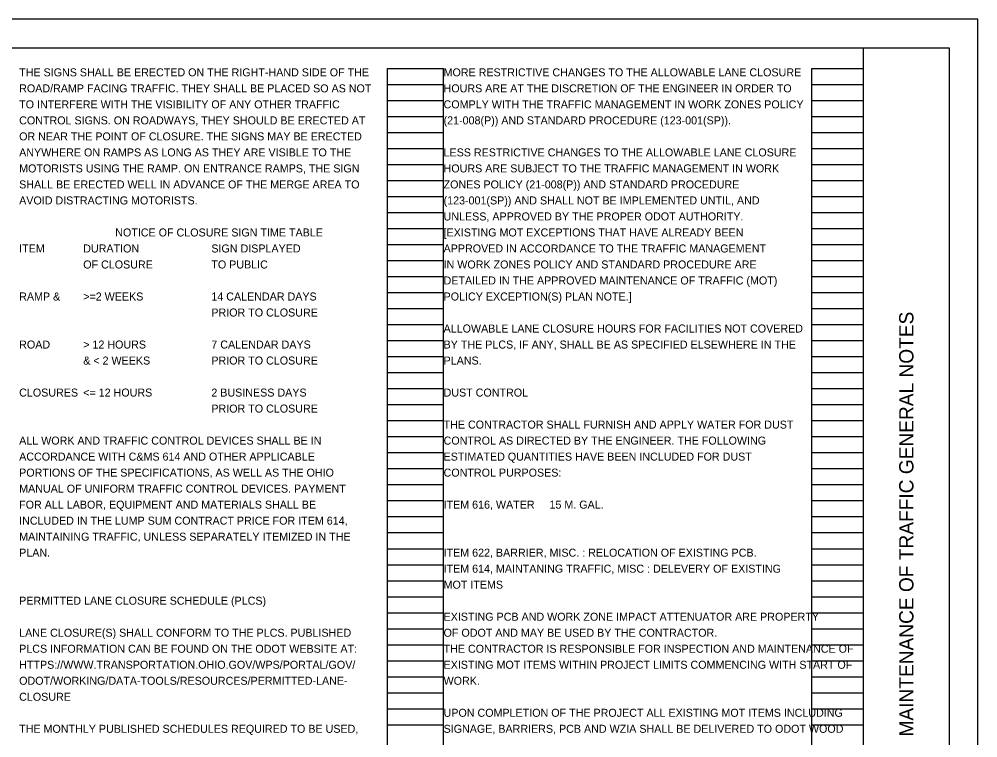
# Model space of a CAD drawing. Extents: x -53 to 237, y -2 to 24.
# Drawn here: x -36.25 to -19.49, y 11.09 to 23.66 of the extents above; entities that cross this region are included whole.
import ezdxf

# ---------------------------------------------------------------- set-up
doc = ezdxf.new("R2010")
doc.units = 0
for name, color, linetype in [('SH_Text', 7, 'Continuous'), ('SN_P_Signs', 7, 'Continuous'), ('SN_X_Text', 7, 'Continuous')]:
    doc.layers.add(name, color=color, linetype=linetype)

msp = doc.modelspace()

# ---------------------------------------------------------------- linework, layer by layer
at = {"layer": 'SH_Text'}
for p, q in [((-29.814, 2.643), (-29.814, 22.803)), ((-29.814, 22.803), (-28.834, 22.803)), ((-28.834, 2.643), (-28.834, 22.803)), ((-22.394, 2.643), (-22.394, 22.803)), ((-22.394, 22.803), (-21.494, 22.803)), ((-21.494, 2.643), (-21.494, 22.803)), ((-29.814, 22.523), (-28.834, 22.523)), ((-22.394, 22.523), (-21.494, 22.523)), ((-29.814, 22.243), (-28.834, 22.243)), ((-22.394, 22.243), (-21.494, 22.243)), ((-29.814, 21.963), (-28.834, 21.963)), ((-22.394, 21.963), (-21.494, 21.963)), ((-29.814, 21.683), (-28.834, 21.683)), ((-22.394, 21.683), (-21.494, 21.683)), ((-29.814, 21.403), (-28.834, 21.403)), ((-22.394, 21.403), (-21.494, 21.403)), ((-29.814, 21.123), (-28.834, 21.123)), ((-22.394, 21.123), (-21.494, 21.123)), ((-29.814, 20.843), (-28.834, 20.843)), ((-22.394, 20.843), (-21.494, 20.843)), ((-29.814, 20.563), (-28.834, 20.563)), ((-22.394, 20.563), (-21.494, 20.563)), ((-29.814, 20.283), (-28.834, 20.283)), ((-22.394, 20.283), (-21.494, 20.283)), ((-29.814, 20.003), (-28.834, 20.003)), ((-22.394, 20.003), (-21.494, 20.003)), ((-29.814, 19.723), (-28.834, 19.723)), ((-22.394, 19.723), (-21.494, 19.723)), ((-29.814, 19.443), (-28.834, 19.443)), ((-22.394, 19.443), (-21.494, 19.443)), ((-29.814, 19.163), (-28.834, 19.163)), ((-22.394, 19.163), (-21.494, 19.163)), ((-29.814, 18.883), (-28.834, 18.883)), ((-22.394, 18.883), (-21.494, 18.883)), ((-29.814, 18.603), (-28.834, 18.603)), ((-22.394, 18.603), (-21.494, 18.603)), ((-29.814, 18.323), (-28.834, 18.323)), ((-22.394, 18.323), (-21.494, 18.323)), ((-29.814, 18.043), (-28.834, 18.043)), ((-22.394, 18.043), (-21.494, 18.043)), ((-29.814, 17.763), (-28.834, 17.763)), ((-22.394, 17.763), (-21.494, 17.763)), ((-29.814, 17.483), (-28.834, 17.483)), ((-22.394, 17.483), (-21.494, 17.483)), ((-29.814, 17.203), (-28.834, 17.203)), ((-22.394, 17.203), (-21.494, 17.203)), ((-29.814, 16.923), (-28.834, 16.923)), ((-22.394, 16.923), (-21.494, 16.923)), ((-29.814, 16.643), (-28.834, 16.643)), ((-22.394, 16.643), (-21.494, 16.643)), ((-29.814, 16.363), (-28.834, 16.363)), ((-22.394, 16.363), (-21.494, 16.363)), ((-29.814, 16.083), (-28.834, 16.083)), ((-22.394, 16.083), (-21.494, 16.083)), ((-29.814, 15.803), (-28.834, 15.803)), ((-22.394, 15.803), (-21.494, 15.803)), ((-29.814, 15.523), (-28.834, 15.523)), ((-22.394, 15.523), (-21.494, 15.523)), ((-29.814, 15.243), (-28.834, 15.243)), ((-22.394, 15.243), (-21.494, 15.243)), ((-29.814, 14.963), (-28.834, 14.963)), ((-22.394, 14.963), (-21.494, 14.963)), ((-29.814, 14.683), (-28.834, 14.683)), ((-22.394, 14.683), (-21.494, 14.683)), ((-29.814, 14.403), (-28.834, 14.403)), ((-22.394, 14.403), (-21.494, 14.403)), ((-29.814, 14.123), (-28.834, 14.123)), ((-22.394, 14.123), (-21.494, 14.123)), ((-29.814, 13.843), (-28.834, 13.843)), ((-22.394, 13.843), (-21.494, 13.843)), ((-29.814, 13.563), (-28.834, 13.563)), ((-22.394, 13.563), (-21.494, 13.563)), ((-29.814, 13.283), (-28.834, 13.283)), ((-22.394, 13.283), (-21.494, 13.283)), ((-29.814, 13.003), (-28.834, 13.003)), ((-22.394, 13.003), (-21.494, 13.003)), ((-29.814, 12.723), (-28.834, 12.723)), ((-22.394, 12.723), (-21.494, 12.723)), ((-29.814, 12.443), (-28.834, 12.443)), ((-22.394, 12.443), (-21.494, 12.443)), ((-29.814, 12.163), (-28.834, 12.163)), ((-22.394, 12.163), (-21.494, 12.163)), ((-29.814, 11.883), (-28.834, 11.883)), ((-22.394, 11.883), (-21.494, 11.883)), ((-29.814, 11.603), (-28.834, 11.603)), ((-22.394, 11.603), (-21.494, 11.603)), ((-29.814, 11.323), (-28.834, 11.323)), ((-22.394, 11.323), (-21.494, 11.323))]:
    msp.add_line(p, q, dxfattribs=at)
at = {"layer": 'SN_X_Text'}
msp.add_line((-21.494, 2.163), (-21.494, 23.163), dxfattribs=at)
for points in [[(-53.494, 1.663), (-19.494, 1.663), (-19.494, 23.663), (-53.494, 23.663)], [(-51.994, 23.163), (-19.994, 23.163), (-19.994, 2.163), (-51.994, 2.163)]]:
    msp.add_lwpolyline(points, close=True, dxfattribs=at)

# ---------------------------------------------------------------- texts
at = {"layer": 'SN_P_Signs'}
for s, p in [('THE SIGNS SHALL BE ERECTED ON THE RIGHT-HAND SIDE OF THE', (-36.254, 22.663)), ('MORE RESTRICTIVE CHANGES TO THE ALLOWABLE LANE CLOSURE', (-28.834, 22.663)), ('ROAD/RAMP FACING TRAFFIC. THEY SHALL BE PLACED SO AS NOT', (-36.254, 22.383)), ('HOURS ARE AT THE DISCRETION OF THE ENGINEER IN ORDER TO', (-28.834, 22.383)), ('TO INTERFERE WITH THE VISIBILITY OF ANY OTHER TRAFFIC', (-36.254, 22.103)), ('COMPLY WITH THE TRAFFIC MANAGEMENT IN WORK ZONES POLICY', (-28.834, 22.103)), ('CONTROL SIGNS. ON ROADWAYS, THEY SHOULD BE ERECTED AT', (-36.254, 21.823)), ('(21-008(P)) AND STANDARD PROCEDURE (123-001(SP)).', (-28.834, 21.823)), ('OR NEAR THE POINT OF CLOSURE. THE SIGNS MAY BE ERECTED', (-36.254, 21.543)), ('ANYWHERE ON RAMPS AS LONG AS THEY ARE VISIBLE TO THE', (-36.254, 21.263)), ('LESS RESTRICTIVE CHANGES TO THE ALLOWABLE LANE CLOSURE', (-28.834, 21.263)), ('MOTORISTS USING THE RAMP. ON ENTRANCE RAMPS, THE SIGN', (-36.254, 20.983)), ('HOURS ARE SUBJECT TO THE TRAFFIC MANAGEMENT IN WORK', (-28.834, 20.983)), ('SHALL BE ERECTED WELL IN ADVANCE OF THE MERGE AREA TO', (-36.254, 20.703)), ('ZONES POLICY (21-008(P)) AND STANDARD PROCEDURE', (-28.834, 20.703)), ('AVOID DISTRACTING MOTORISTS.', (-36.254, 20.423)), ('(123-001(SP)) AND SHALL NOT BE IMPLEMENTED UNTIL, AND', (-28.834, 20.423)), ('UNLESS, APPROVED BY THE PROPER ODOT AUTHORITY.', (-28.834, 20.143)), ('NOTICE OF CLOSURE SIGN TIME TABLE', (-34.574, 19.863)), ('[EXISTING MOT EXCEPTIONS THAT HAVE ALREADY BEEN', (-28.834, 19.863)), ('ITEM       ', (-36.254, 19.583)), ('DURATION       ', (-35.134, 19.583)), ('SIGN DISPLAYED', (-32.894, 19.583)), ('APPROVED IN ACCORDANCE TO THE TRAFFIC MANAGEMENT', (-28.834, 19.583)), ('OF CLOSURE     ', (-35.134, 19.303)), ('TO PUBLIC', (-32.894, 19.303)), ('IN WORK ZONES POLICY AND STANDARD PROCEDURE ARE', (-28.834, 19.303)), ('DETAILED IN THE APPROVED MAINTENANCE OF TRAFFIC (MOT)', (-28.834, 19.023)), ('RAMP &     ', (-36.254, 18.743)), ('>=2 WEEKS      ', (-35.134, 18.743)), ('14 CALENDAR DAYS', (-32.894, 18.743)), ('POLICY EXCEPTION(S) PLAN NOTE.]', (-28.834, 18.743)), ('PRIOR TO CLOSURE', (-32.894, 18.463)), ('ALLOWABLE LANE CLOSURE HOURS FOR FACILITIES NOT COVERED', (-28.834, 18.183)), ('ROAD       ', (-36.254, 17.903)), ('> 12 HOURS     ', (-35.134, 17.903)), ('7 CALENDAR DAYS', (-32.894, 17.903)), ('BY THE PLCS, IF ANY, SHALL BE AS SPECIFIED ELSEWHERE IN THE', (-28.834, 17.903)), ('& < 2 WEEKS    ', (-35.134, 17.623)), ('PRIOR TO CLOSURE', (-32.894, 17.623)), ('PLANS.', (-28.834, 17.623)), ('CLOSURES   ', (-36.254, 17.063)), ('<= 12 HOURS    ', (-35.134, 17.063)), ('2 BUSINESS DAYS', (-32.894, 17.063)), ('DUST CONTROL', (-28.834, 17.063)), ('PRIOR TO CLOSURE', (-32.894, 16.783)), ('THE CONTRACTOR SHALL FURNISH AND APPLY WATER FOR DUST', (-28.834, 16.503)), ('ALL WORK AND TRAFFIC CONTROL DEVICES SHALL BE IN', (-36.254, 16.223)), ('CONTROL AS DIRECTED BY THE ENGINEER. THE FOLLOWING', (-28.834, 16.223)), ('ACCORDANCE WITH C&MS 614 AND OTHER APPLICABLE', (-36.254, 15.943)), ('ESTIMATED QUANTITIES HAVE BEEN INCLUDED FOR DUST', (-28.834, 15.943)), ('PORTIONS OF THE SPECIFICATIONS, AS WELL AS THE OHIO', (-36.254, 15.663)), ('CONTROL PURPOSES:', (-28.834, 15.663)), ('MANUAL OF UNIFORM TRAFFIC CONTROL DEVICES. PAYMENT', (-36.254, 15.383)), ('FOR ALL LABOR, EQUIPMENT AND MATERIALS SHALL BE', (-36.254, 15.103)), ('ITEM 616, WATER     15 M. GAL.', (-28.834, 15.103)), ('INCLUDED IN THE LUMP SUM CONTRACT PRICE FOR ITEM 614,', (-36.254, 14.823)), ('MAINTAINING TRAFFIC, UNLESS SEPARATELY ITEMIZED IN THE', (-36.254, 14.543)), ('PLAN.', (-36.254, 14.263)), ('ITEM 622, BARRIER, MISC. : RELOCATION OF EXISTING PCB.', (-28.834, 14.263)), ('ITEM 614, MAINTANING TRAFFIC, MISC : DELEVERY OF EXISTING', (-28.834, 13.983)), ('MOT ITEMS', (-28.834, 13.703)), ('PERMITTED LANE CLOSURE SCHEDULE (PLCS)', (-36.254, 13.423)), ('EXISTING PCB AND WORK ZONE IMPACT ATTENUATOR ARE PROPERTY', (-28.834, 13.143)), ('LANE CLOSURE(S) SHALL CONFORM TO THE PLCS. PUBLISHED', (-36.254, 12.863)), ('OF ODOT AND MAY BE USED BY THE CONTRACTOR.', (-28.834, 12.863)), ('PLCS INFORMATION CAN BE FOUND ON THE ODOT WEBSITE AT:', (-36.254, 12.583)), ('THE CONTRACTOR IS RESPONSIBLE FOR INSPECTION AND MAINTENANCE OF', (-28.834, 12.583)), ('HTTPS://WWW.TRANSPORTATION.OHIO.GOV/WPS/PORTAL/GOV/', (-36.254, 12.303)), ('EXISTING MOT ITEMS WITHIN PROJECT LIMITS COMMENCING WITH START OF', (-28.834, 12.303)), ('ODOT/WORKING/DATA-TOOLS/RESOURCES/PERMITTED-LANE-', (-36.254, 12.023)), ('WORK.', (-28.834, 12.023)), ('CLOSURE', (-36.254, 11.743)), ('UPON COMPLETION OF THE PROJECT ALL EXISTING MOT ITEMS INCLUDING', (-28.834, 11.463)), ('THE MONTHLY PUBLISHED SCHEDULES REQUIRED TO BE USED,', (-36.254, 11.183)), ('SIGNAGE, BARRIERS, PCB AND WZIA SHALL BE DELIVERED TO ODOT WOOD', (-28.834, 11.183))]:
    msp.add_text(s, height=0.14, dxfattribs=at).set_placement(p)
at = {"layer": 'SN_X_Text'}
msp.add_text('MAINTENANCE OF TRAFFIC GENERAL NOTES', height=0.25, rotation=90, dxfattribs=at).set_placement((-20.619, 11.118))

doc.saveas('drawing.dxf')
